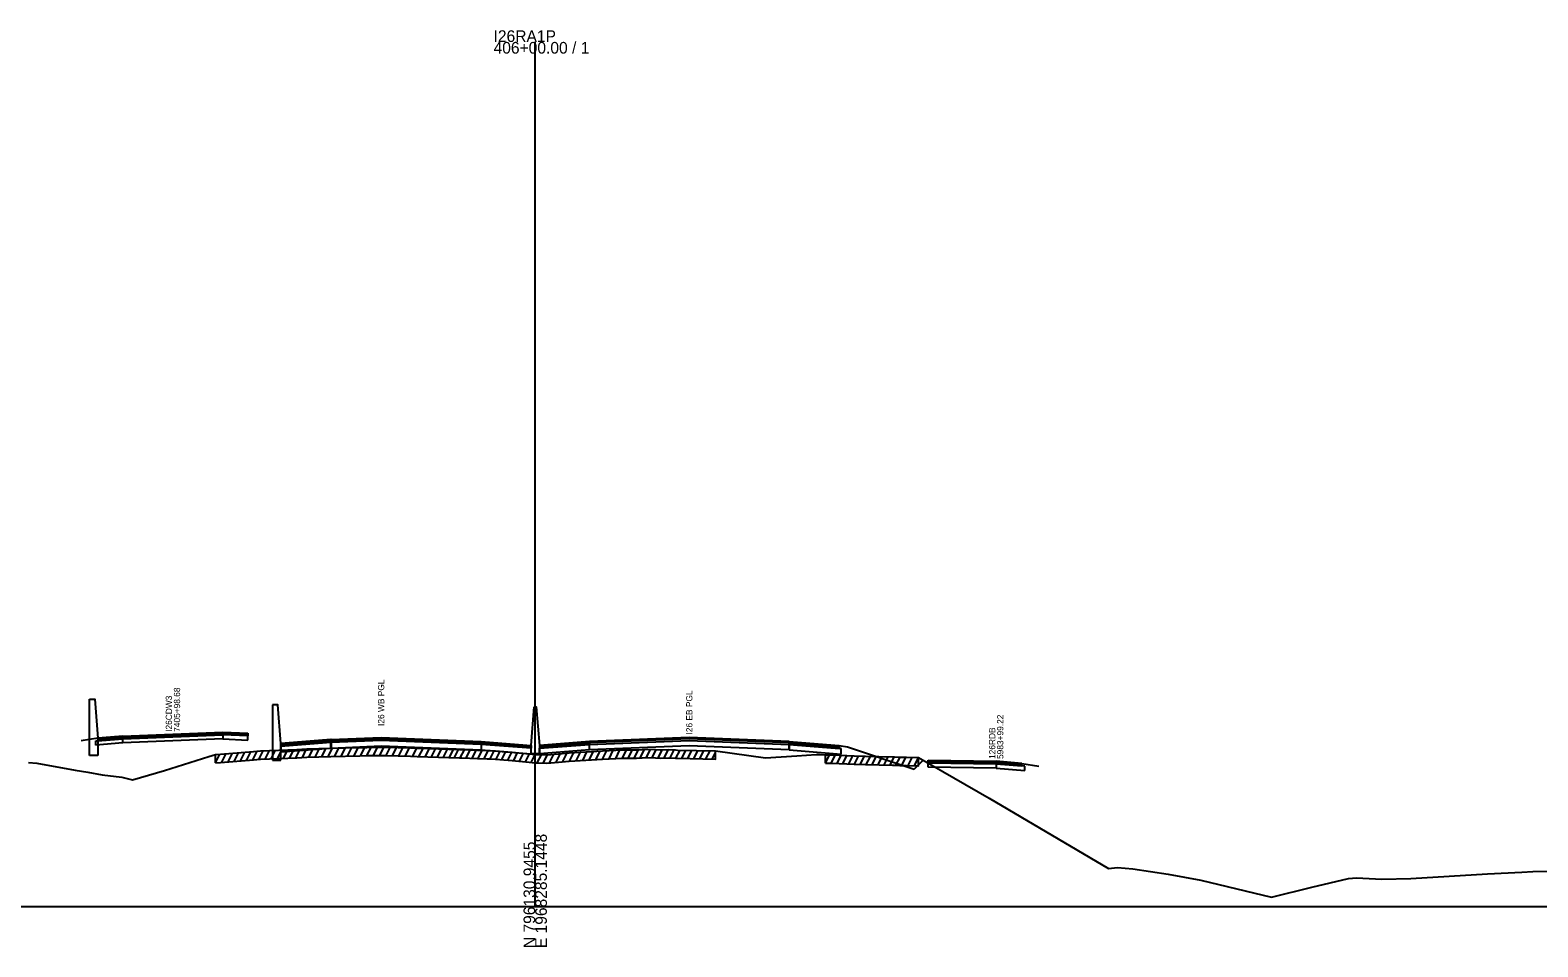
# Model space of a CAD drawing. Extents: x 1017 to 19997, y -1947 to 50737.
# Drawn here: x 16478.7 to 16840.8, y 5990.3 to 6210.6 of the extents above; entities that cross this region are included whole.
import ezdxf

# ---------------------------------------------------------------- set-up
doc = ezdxf.new("R2010")
doc.units = 0
for name, color, linetype in [('RD_GPK_XS_Cell', 7, 'Continuous'), ('RD_XS_Base', 7, 'Continuous'), ('RD_XS_ExGround', 7, 'Continuous'), ('RD_XS_ExPaveRet', 7, 'Continuous'), ('RD_XS_Greenside', 7, 'Continuous'), ('RD_XS_MedBWall', 7, 'Continuous'), ('RD_XS_Pave', 7, 'Continuous'), ('RD_XS_PaveOvlay', 7, 'Continuous'), ('RD_XS_TieSlope', 7, 'Continuous'), ('RD_XS_TX_Notes', 7, 'Continuous')]:
    doc.layers.add(name, color=color, linetype=linetype)

msp = doc.modelspace()

# ---------------------------------------------------------------- linework, layer by layer
at = {"layer": 'RD_GPK_XS_Cell'}
for p, q in [((16600, 6000), (16600, 6207.74)), ((16000, 6000), (16600, 6000)), ((16600, 6000), (17200, 6000))]:
    msp.add_line(p, q, dxfattribs=at)
at = {"layer": 'RD_XS_Base'}
for points in [[(16494.5, 6039.78), (16495, 6039.82), (16501, 6040.31)], [(16494.5, 6038.78), (16494.5, 6039.78)], [(16501, 6039.31), (16494.5, 6038.78)], [(16501, 6039.31), (16501, 6040.31)], [(16525, 6040.26), (16513, 6039.78), (16501, 6039.31)], [(16525, 6041.26), (16525, 6040.26)], [(16525, 6040.26), (16531, 6040.01)], [(16531, 6040.01), (16531, 6041.01)], [(16550.95, 6039.43), (16538.95, 6038.47)], [(16550.95, 6038.09), (16550.95, 6039.43)], [(16551, 6039.43), (16551, 6038.09)], [(16538.95, 6038.47), (16538.95, 6037.13)], [(16538.95, 6037.13), (16550.95, 6038.09)], [(16551, 6038.09), (16550.95, 6038.09)], [(16551, 6038.09), (16563, 6038.59), (16587, 6037.62)], [(16599, 6038.02), (16587, 6038.96)], [(16587, 6038.96), (16587, 6037.62)], [(16587, 6037.62), (16599, 6036.68)], [(16599, 6036.68), (16599, 6038.02)], [(16601, 6036.68), (16601, 6038.02)], [(16613, 6037.62), (16601, 6036.68)], [(16613, 6037.62), (16613, 6038.96)], [(16660.95, 6037.62), (16637, 6038.59), (16613, 6037.62)], [(16660.95, 6037.62), (16660.95, 6038.96)], [(16661, 6037.62), (16660.95, 6037.62)], [(16661, 6038.96), (16661, 6037.62)], [(16673.5, 6037.97), (16673, 6038.01), (16661, 6038.96)], [(16661, 6037.62), (16673.5, 6036.63)], [(16673.5, 6036.63), (16673.5, 6037.97)], [(16694.35, 6033.52), (16694.35, 6034.52)], [(16710.7, 6033.27), (16694.35, 6033.52)], [(16710.7, 6034.27), (16710.7, 6033.27)], [(16717.55, 6033.71), (16716.84, 6033.77), (16710.7, 6034.27)], [(16710.7, 6033.27), (16717.55, 6032.71)], [(16717.55, 6032.71), (16717.55, 6033.71)]]:
    msp.add_lwpolyline(points, dxfattribs=at)
at = {"layer": 'RD_XS_ExGround'}
msp.add_lwpolyline([(16478.33, 6034.62), (16480.31, 6034.48), (16489.52, 6032.78), (16492.56, 6032.28), (16496.01, 6031.67), (16500.71, 6031.07), (16503.31, 6030.43), (16510.95, 6032.67), (16521.65, 6036.03), (16523.26, 6036.53), (16524.46, 6036.63), (16532.34, 6037.24), (16533.17, 6037.3), (16534.04, 6037.39), (16542.72, 6037.76), (16545.15, 6037.86), (16550.89, 6038.03), (16557.89, 6038.24), (16559.55, 6038.25), (16564.05, 6038.28), (16570.05, 6038.1), (16571.68, 6038.05), (16581.83, 6037.73), (16582.37, 6037.72), (16586.13, 6037.54), (16588.49, 6037.51), (16589.18, 6037.5), (16590.46, 6037.4), (16594.47, 6037.11), (16598.57, 6036.67), (16600.03, 6036.51), (16600.76, 6036.5), (16602.82, 6036.45), (16605.56, 6036.72), (16608.15, 6036.94), (16616.16, 6037.39), (16620.98, 6037.66), (16622.93, 6037.65), (16623.52, 6037.64), (16624.36, 6037.67), (16627.03, 6037.78), (16628.9, 6037.72), (16630, 6037.66), (16631.9, 6037.76), (16633.68, 6037.62), (16634.21, 6037.61), (16643.29, 6037.4), (16647.33, 6036.83), (16655.32, 6035.75), (16662.85, 6036.22), (16667.46, 6036.5), (16668.49, 6036.5), (16669.69, 6036.48), (16670.6, 6036.46), (16671.23, 6036.45), (16676.57, 6036.19), (16679.35, 6036.09), (16685.81, 6035.98), (16686.32, 6035.98), (16687.59, 6035.92), (16689.19, 6035.87), (16692.05, 6035.78), (16708.98, 6026.06), (16737.68, 6009.17), (16739.84, 6009.36), (16743.54, 6009.04), (16752.02, 6007.74), (16759.81, 6006.31), (16776.82, 6002.21), (16786.54, 6004.65), (16795.28, 6006.73), (16797.19, 6006.88), (16803.3, 6006.55), (16810.29, 6006.72), (16828.66, 6007.89), (16836.9, 6008.27), (16839.58, 6008.41), (16844.95, 6008.46)], dxfattribs=at)
at = {"layer": 'RD_XS_ExPaveRet'}
for p, q in [((16523.26, 6034.53), (16524.3, 6036.62)), ((16523.26, 6034.53), (16523.26, 6036.53)), ((16524.75, 6034.65), (16525.79, 6036.73)), ((16526.23, 6034.77), (16527.27, 6036.85)), ((16527.71, 6034.88), (16528.75, 6036.96)), ((16529.2, 6035), (16530.24, 6037.08)), ((16530.68, 6035.11), (16531.72, 6037.19)), ((16532.17, 6035.23), (16533.21, 6037.31)), ((16533.67, 6035.35), (16534.71, 6037.42)), ((16535.16, 6035.44), (16536.18, 6037.48)), ((16536.63, 6035.5), (16537.65, 6037.54)), ((16538.1, 6035.56), (16539.12, 6037.61)), ((16539.57, 6035.62), (16540.6, 6037.67)), ((16541.05, 6035.69), (16542.07, 6037.73)), ((16542.52, 6035.75), (16543.55, 6037.79)), ((16544.08, 6035.81), (16545.1, 6037.86)), ((16545.63, 6035.88), (16546.65, 6037.91)), ((16547.18, 6035.92), (16548.2, 6037.95)), ((16548.74, 6035.97), (16549.75, 6038)), ((16550.29, 6036.01), (16551.3, 6038.04)), ((16551.84, 6036.06), (16552.85, 6038.09)), ((16553.39, 6036.1), (16554.41, 6038.13)), ((16554.94, 6036.15), (16555.96, 6038.18)), ((16556.5, 6036.2), (16557.52, 6038.23)), ((16558.06, 6036.24), (16559.06, 6038.24)), ((16559.6, 6036.25), (16560.6, 6038.25)), ((16561.14, 6036.26), (16562.14, 6038.26)), ((16562.68, 6036.27), (16563.68, 6038.27)), ((16564.22, 6036.27), (16565.2, 6038.24)), ((16565.73, 6036.23), (16566.71, 6038.2)), ((16567.24, 6036.18), (16568.22, 6038.15)), ((16568.81, 6036.14), (16569.8, 6038.11)), ((16570.56, 6036.08), (16571.54, 6038.05)), ((16572.07, 6036.04), (16573.06, 6038.01)), ((16573.59, 6035.99), (16574.58, 6037.96)), ((16575.06, 6035.95), (16576.05, 6037.91)), ((16576.53, 6035.9), (16577.51, 6037.87)), ((16577.96, 6035.86), (16578.94, 6037.82)), ((16579.38, 6035.81), (16580.36, 6037.78)), ((16580.62, 6035.77), (16581.6, 6037.74)), ((16582.01, 6035.73), (16582.99, 6037.69)), ((16583.44, 6035.67), (16584.41, 6037.62)), ((16584.86, 6035.6), (16585.84, 6037.56)), ((16586.29, 6035.54), (16587.29, 6037.53)), ((16587.74, 6035.52), (16588.74, 6037.51)), ((16589.19, 6035.5), (16590.15, 6037.43)), ((16590.6, 6035.39), (16591.56, 6037.32)), ((16592, 6035.29), (16592.97, 6037.22)), ((16593.41, 6035.19), (16594.37, 6037.11)), ((16594.83, 6035.07), (16595.78, 6036.97)), ((16596.24, 6034.92), (16597.19, 6036.81)), ((16597.65, 6034.76), (16598.6, 6036.66)), ((16599.06, 6034.61), (16600.01, 6036.52)), ((16600.49, 6034.51), (16601.48, 6036.48)), ((16601.95, 6034.47), (16602.95, 6036.46)), ((16603.46, 6034.51), (16604.51, 6036.62)), ((16605.02, 6034.67), (16606.07, 6036.77)), ((16606.63, 6034.81), (16607.67, 6036.9)), ((16608.23, 6034.94), (16609.26, 6037)), ((16609.82, 6035.03), (16610.85, 6037.09)), ((16611.4, 6035.12), (16612.43, 6037.18)), ((16612.98, 6035.21), (16614.01, 6037.27)), ((16614.57, 6035.3), (16615.6, 6037.36)), ((16616.15, 6035.39), (16617.18, 6037.45)), ((16617.73, 6035.48), (16618.76, 6037.54)), ((16619.33, 6035.57), (16620.36, 6037.63)), ((16620.93, 6035.66), (16621.93, 6037.66)), ((16622.35, 6035.65), (16623.34, 6037.64)), ((16623.77, 6035.65), (16624.79, 6037.68)), ((16625.23, 6035.7), (16626.25, 6037.75)), ((16626.68, 6035.76), (16627.68, 6037.76)), ((16628.09, 6035.74), (16629.08, 6037.71)), ((16629.5, 6035.68), (16630.5, 6037.68)), ((16630.95, 6035.71), (16631.97, 6037.75)), ((16632.4, 6035.72), (16633.36, 6037.64)), ((16633.79, 6035.62), (16634.78, 6037.59)), ((16635.21, 6035.58), (16636.2, 6037.56)), ((16636.64, 6035.55), (16637.63, 6037.53)), ((16638.07, 6035.52), (16639.06, 6037.5)), ((16639.5, 6035.49), (16640.49, 6037.47)), ((16641, 6035.45), (16641.99, 6037.43)), ((16642.51, 6035.42), (16643.29, 6036.99)), ((16643.29, 6035.4), (16643.29, 6037.4)), ((16669.69, 6034.48), (16669.69, 6036.48)), ((16669.69, 6034.48), (16670.67, 6036.46)), ((16671.1, 6034.45), (16672.08, 6036.41)), ((16672.49, 6034.39), (16673.47, 6036.34)), ((16673.88, 6034.32), (16674.86, 6036.28)), ((16675.28, 6034.26), (16676.25, 6036.21)), ((16676.67, 6034.19), (16677.65, 6036.16)), ((16678.07, 6034.14), (16679.06, 6036.1)), ((16679.49, 6034.09), (16680.48, 6036.07)), ((16680.92, 6034.07), (16681.91, 6036.05)), ((16682.35, 6034.04), (16683.34, 6036.03)), ((16683.78, 6034.02), (16684.77, 6036)), ((16685.21, 6033.99), (16686.2, 6035.98)), ((16686.64, 6033.96), (16687.61, 6035.92)), ((16688.05, 6033.91), (16689.04, 6035.88)), ((16689.55, 6033.86), (16690.53, 6035.83)), ((16691.05, 6033.81), (16692.03, 6035.78)), ((16692.05, 6033.78), (16692.05, 6035.78))]:
    msp.add_line(p, q, dxfattribs=at)
for points in [[(16523.26, 6034.53), (16524.46, 6034.63), (16532.34, 6035.24), (16533.17, 6035.3), (16534.04, 6035.39), (16542.72, 6035.76), (16545.15, 6035.86), (16550.89, 6036.03), (16557.89, 6036.24), (16559.55, 6036.25), (16564.05, 6036.28), (16570.05, 6036.1), (16571.68, 6036.05), (16581.83, 6035.73), (16582.37, 6035.72), (16586.13, 6035.54), (16588.49, 6035.51), (16589.18, 6035.5), (16590.46, 6035.4), (16594.47, 6035.11), (16598.57, 6034.67), (16600.03, 6034.51), (16600.76, 6034.5), (16602.82, 6034.45), (16605.56, 6034.72), (16608.15, 6034.94), (16616.16, 6035.39), (16620.98, 6035.66), (16622.93, 6035.65), (16623.52, 6035.64), (16624.36, 6035.67), (16627.03, 6035.78), (16628.9, 6035.72), (16630, 6035.66), (16631.9, 6035.76), (16633.68, 6035.62), (16634.21, 6035.61), (16643.29, 6035.4), (16643.29, 6035.4)], [(16669.69, 6034.48), (16670.6, 6034.46), (16671.23, 6034.45), (16676.57, 6034.19), (16679.35, 6034.09), (16685.81, 6033.98), (16686.32, 6033.98), (16687.59, 6033.92), (16689.19, 6033.87), (16692.05, 6033.78), (16692.05, 6033.78)]]:
    msp.add_lwpolyline(points, dxfattribs=at)
at = {"layer": 'RD_XS_Greenside'}
for points in [[(16495, 6040.46), (16491, 6039.82)], [(16673, 6038.67), (16675, 6038.34)], [(16675, 6038.34), (16691, 6033.01)], [(16716.84, 6034.4), (16720.93, 6033.75)]]:
    msp.add_lwpolyline(points, dxfattribs=at)
at = {"layer": 'RD_XS_MedBWall'}
for points in [[(16493, 6036.32), (16493, 6049.8)], [(16493, 6049.8), (16494.25, 6049.8), (16495, 6040.46)], [(16538.95, 6039.15), (16538.2, 6048.49), (16536.95, 6048.49)], [(16536.95, 6048.49), (16536.95, 6035.15)], [(16599, 6038.67), (16599.75, 6048.01)], [(16599.75, 6048.01), (16600.25, 6048.01), (16601, 6038.67)], [(16495, 6040.46), (16495, 6036.32)], [(16495, 6036.32), (16493, 6036.32)], [(16538.95, 6035.15), (16538.95, 6039.15)], [(16599, 6036.67), (16599, 6038.02), (16599, 6038.67)], [(16601, 6036.67), (16599, 6036.67)], [(16601, 6038.67), (16601, 6038.02), (16601, 6036.67)], [(16536.95, 6035.15), (16538.95, 6035.15)]]:
    msp.add_lwpolyline(points, dxfattribs=at)
at = {"layer": 'RD_XS_Pave'}
for points in [[(16495, 6040.14), (16501, 6040.62)], [(16501, 6040.31), (16495, 6039.82)], [(16495, 6039.82), (16495, 6040.14)], [(16525, 6041.58), (16513, 6041.1), (16501, 6040.62)], [(16501, 6040.31), (16513, 6040.78), (16525, 6041.26)], [(16501, 6040.62), (16501, 6040.31)], [(16525, 6041.26), (16525, 6041.58)], [(16525, 6041.58), (16531, 6041.34)], [(16531, 6041.01), (16525, 6041.26)], [(16531, 6041.34), (16531, 6041.01)], [(16550.95, 6039.77), (16538.95, 6038.81)], [(16550.95, 6039.77), (16551, 6039.77)], [(16550.95, 6039.43), (16550.95, 6039.77)], [(16551, 6039.43), (16550.95, 6039.43)], [(16587, 6038.96), (16563, 6039.93), (16551, 6039.43)], [(16551, 6039.77), (16551, 6039.43)], [(16587, 6039.3), (16587, 6038.96)], [(16587, 6039.3), (16599, 6038.36)], [(16660.95, 6039.3), (16637, 6040.26), (16613, 6039.3)], [(16613, 6038.96), (16637, 6039.93), (16660.95, 6038.96)], [(16613, 6039.3), (16613, 6038.96)], [(16660.95, 6039.3), (16661, 6039.3)], [(16660.95, 6038.96), (16660.95, 6039.3)], [(16661, 6039.3), (16661, 6038.96)], [(16538.95, 6038.81), (16538.95, 6038.47)], [(16599, 6038.36), (16599, 6038.02)], [(16601, 6038.02), (16613, 6038.96)], [(16601, 6038.36), (16601, 6038.02)], [(16661, 6038.96), (16660.95, 6038.96)], [(16661, 6038.96), (16673, 6038.01)], [(16673, 6038.01), (16673, 6038.34)], [(16710.7, 6034.59), (16694.35, 6034.83)], [(16694.35, 6034.83), (16694.35, 6034.52)], [(16694.35, 6034.52), (16710.7, 6034.27)], [(16710.7, 6034.27), (16710.7, 6034.59)], [(16716.84, 6034.09), (16710.7, 6034.59)], [(16710.7, 6034.27), (16716.84, 6033.77)], [(16716.84, 6033.77), (16716.84, 6034.09)]]:
    msp.add_lwpolyline(points, dxfattribs=at)
at = {"layer": 'RD_XS_PaveOvlay'}
for points in [[(16501, 6040.94), (16495, 6040.46)], [(16495, 6040.46), (16495, 6040.14)], [(16501, 6040.94), (16513, 6041.42), (16525, 6041.9)], [(16501, 6040.62), (16501, 6040.94)], [(16525, 6041.9), (16525, 6041.58)], [(16525, 6041.9), (16531, 6041.66)], [(16531, 6041.66), (16531, 6041.34)], [(16550.95, 6040.11), (16538.95, 6039.15)], [(16551, 6040.11), (16550.95, 6040.11)], [(16550.95, 6040.11), (16550.95, 6039.77)], [(16551, 6040.11), (16563, 6040.59), (16587, 6039.63)], [(16587, 6039.3), (16563, 6040.26), (16551, 6039.77)], [(16551, 6039.77), (16551, 6040.11)], [(16587, 6039.63), (16587, 6039.3)], [(16587, 6039.63), (16599, 6038.67)], [(16613, 6039.63), (16601, 6038.67)], [(16601, 6038.36), (16613, 6039.3)], [(16660.95, 6039.64), (16637, 6040.59), (16613, 6039.63)], [(16613, 6039.3), (16613, 6039.63)], [(16660.95, 6039.64), (16661, 6039.63)], [(16660.95, 6039.3), (16660.95, 6039.64)], [(16661, 6039.63), (16673, 6038.67)], [(16661, 6039.3), (16661, 6039.63)], [(16673, 6038.34), (16661, 6039.3)], [(16538.95, 6039.15), (16538.95, 6038.81)], [(16599, 6038.67), (16599, 6038.36)], [(16601, 6038.67), (16601, 6038.36)], [(16673, 6038.67), (16673, 6038.34)], [(16694.35, 6035.15), (16710.7, 6034.9)], [(16694.35, 6034.83), (16694.35, 6035.15)], [(16710.7, 6034.9), (16710.7, 6034.59)], [(16716.84, 6034.4), (16710.7, 6034.9)], [(16716.84, 6034.09), (16716.84, 6034.4)]]:
    msp.add_lwpolyline(points, dxfattribs=at)
at = {"layer": 'RD_XS_TieSlope'}
msp.add_lwpolyline([(16691, 6033.01), (16693.14, 6035.15)], dxfattribs=at)

# ---------------------------------------------------------------- texts
at = {"layer": 'RD_GPK_XS_Cell'}
for s, p in [('I26RA1P', (16590, 6207.74)), ('406+00.00 / 1', (16590, 6204.94))]:
    msp.add_text(s, height=2.8, dxfattribs=at).set_placement(p)
for s, p in [('N 796130.9455', (16600, 5990)), ('E 1968285.1448', (16602.8, 5990))]:
    msp.add_text(s, height=2.8, rotation=90, dxfattribs=at).set_placement(p)
at = {"layer": 'RD_XS_TX_Notes'}
for s, p in [('I26 WB PGL', (16563.75, 6043.39)), (' I26CDW3', (16512.77, 6041.42)), (' 7405+98.68', (16514.73, 6041.42)), ('I26 EB PGL', (16637.75, 6041.33)), (' 126RDB', (16710.48, 6034.9)), (' 5983+99.22', (16712.43, 6034.9))]:
    msp.add_text(s, height=1.5, rotation=90, dxfattribs=at).set_placement(p)

doc.saveas('drawing.dxf')
